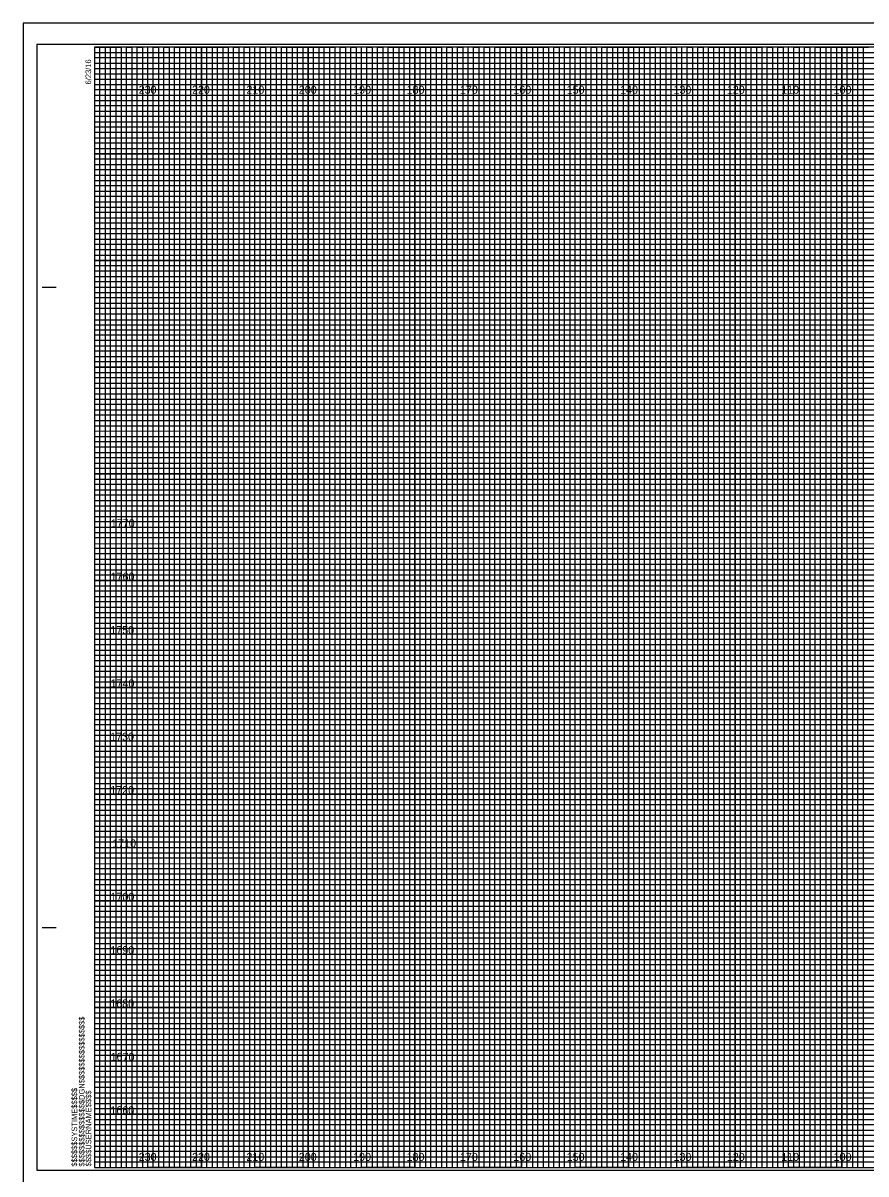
# Model space of a CAD drawing. Extents: x -13 to 1780, y -15 to 3284.
# Drawn here: x 726.7 to 884.6, y 214.9 to 430.6 of the extents above; entities that cross this region are included whole.
import ezdxf

# ---------------------------------------------------------------- set-up
doc = ezdxf.new("R2010")
doc.units = 0
for name, color, linetype in [('Prop Retaining Wall', 7, 'Continuous'), ('Prop SS Cut Line', 7, 'Continuous'), ('Prop SS Fill Line', 7, 'Continuous'), ('Prop SS Transition Line', 7, 'Continuous'), ('Prop XS Earthwork Shape', 7, 'Continuous'), ('Prop XS Noise Wall', 7, 'Continuous'), ('Prop XS Station Labels', 7, 'Continuous'), ('Raster_Level_0', 7, 'Continuous'), ('Scratch_Level_3', 7, 'Continuous'), ('Scratch_Level_7', 7, 'Continuous'), ('Typical Bridge Rail CELL', 7, 'Continuous')]:
    doc.layers.add(name, color=color, linetype=linetype)

msp = doc.modelspace()

# ---------------------------------------------------------------- linework, layer by layer
at = {"layer": 'Prop Retaining Wall'}
for p, q in [((730.26, 381.12), (732.76, 381.12)), ((730.36, 381.12), (732.86, 381.12)), ((730.26, 261.12), (732.76, 261.12)), ((730.36, 261.12), (732.86, 261.12)), ((740.06, 216.12), (740.06, 216.12)), ((740.06, 216.12), (740.06, 216.12)), ((740.06, 216.12), (740.06, 216.12)), ((740.06, 216.12), (740.06, 216.12)), ((740.06, 216.12), (740.06, 216.12)), ((740.06, 216.12), (740.06, 216.12)), ((740.06, 216.12), (740.06, 216.12))]:
    msp.add_line(p, q, dxfattribs=at)
msp.add_lwpolyline([(1060.06, 426.12), (740.06, 426.12), (740.06, 216.12), (1060.06, 216.12)], close=True, dxfattribs=at)
at = {"layer": 'Prop SS Cut Line'}
for points in [[(740.06, 426.12), (745.06, 426.12), (745.06, 216.12), (755.06, 216.12), (755.06, 426.12), (765.06, 426.12), (765.06, 216.12), (775.06, 216.12), (775.06, 426.12), (785.06, 426.12), (785.06, 216.12), (795.06, 216.12), (795.06, 426.12), (805.06, 426.12), (805.06, 216.12), (815.06, 216.12), (815.06, 426.12), (825.06, 426.12), (825.06, 216.12), (835.06, 216.12), (835.06, 426.12), (845.06, 426.12), (845.06, 216.12), (855.06, 216.12), (855.06, 426.12), (865.06, 426.12), (865.06, 216.12), (875.06, 216.12), (875.06, 426.12), (885.06, 426.12)], [(740.06, 421.12), (1015.06, 421.12)], [(740.06, 401.12), (1060.06, 401.12), (1060.06, 411.12), (740.06, 411.12)], [(740.06, 381.12), (1060.06, 381.12), (1060.06, 391.12), (740.06, 391.12)], [(740.06, 361.12), (1060.06, 361.12), (1060.06, 371.12), (740.06, 371.12)], [(740.06, 341.12), (1060.06, 341.12), (1060.06, 351.12), (740.06, 351.12)], [(740.06, 321.12), (1060.06, 321.12), (1060.06, 331.12), (740.06, 331.12)], [(740.06, 301.12), (1060.06, 301.12), (1060.06, 311.12), (740.06, 311.12)], [(740.06, 281.12), (1060.06, 281.12), (1060.06, 291.12), (740.06, 291.12)], [(740.06, 261.12), (1060.06, 261.12), (1060.06, 271.12), (740.06, 271.12)], [(740.06, 241.12), (1060.06, 241.12), (1060.06, 251.12), (740.06, 251.12)], [(740.06, 221.12), (1060.06, 221.12), (1060.06, 231.12), (740.06, 231.12)]]:
    msp.add_lwpolyline(points, dxfattribs=at)
at = {"layer": 'Prop SS Fill Line'}
for p, q in [((750.06, 426.12), (740.06, 426.12)), ((750.06, 216.12), (750.06, 426.12)), ((770.06, 426.12), (760.06, 426.12)), ((760.06, 426.12), (760.06, 216.12)), ((770.06, 216.12), (770.06, 426.12)), ((790.06, 426.12), (780.06, 426.12)), ((780.06, 426.12), (780.06, 216.12)), ((790.06, 216.12), (790.06, 426.12)), ((810.06, 426.12), (800.06, 426.12)), ((800.06, 426.12), (800.06, 216.12)), ((810.06, 216.12), (810.06, 426.12)), ((830.06, 426.12), (820.06, 426.12)), ((820.06, 426.12), (820.06, 216.12)), ((830.06, 216.12), (830.06, 426.12)), ((850.06, 426.12), (840.06, 426.12)), ((840.06, 426.12), (840.06, 216.12)), ((850.06, 216.12), (850.06, 426.12)), ((870.06, 426.12), (860.06, 426.12)), ((860.06, 426.12), (860.06, 216.12)), ((870.06, 216.12), (870.06, 426.12)), ((890.06, 426.12), (880.06, 426.12)), ((880.06, 426.12), (880.06, 216.12)), ((760.06, 216.12), (750.06, 216.12)), ((780.06, 216.12), (770.06, 216.12)), ((800.06, 216.12), (790.06, 216.12)), ((820.06, 216.12), (810.06, 216.12)), ((840.06, 216.12), (830.06, 216.12)), ((860.06, 216.12), (850.06, 216.12)), ((880.06, 216.12), (870.06, 216.12))]:
    msp.add_line(p, q, dxfattribs=at)
for points in [[(740.06, 416.12), (1060.06, 416.12), (1060.06, 406.12), (740.06, 406.12)], [(740.06, 396.12), (1060.06, 396.12), (1060.06, 386.12), (740.06, 386.12)], [(740.06, 376.12), (1060.06, 376.12), (1060.06, 366.12), (740.06, 366.12)], [(740.06, 356.12), (1060.06, 356.12), (1060.06, 346.12), (740.06, 346.12)], [(740.06, 336.12), (1060.06, 336.12), (1060.06, 326.12), (740.06, 326.12)], [(740.06, 316.12), (1060.06, 316.12), (1060.06, 306.12), (740.06, 306.12)], [(740.06, 296.12), (1060.06, 296.12), (1060.06, 286.12), (740.06, 286.12)], [(740.06, 276.12), (1060.06, 276.12), (1060.06, 266.12), (740.06, 266.12)], [(740.06, 256.12), (1060.06, 256.12), (1060.06, 246.12), (740.06, 246.12)], [(740.06, 236.12), (1060.06, 236.12), (1060.06, 226.12), (740.06, 226.12)]]:
    msp.add_lwpolyline(points, dxfattribs=at)
at = {"layer": 'Prop SS Transition Line'}
for p, q in [((740.06, 425.12), (1000.06, 425.12)), ((1000.06, 424.1), (740.06, 424.1)), ((740.06, 424.1), (740.06, 423.12)), ((740.06, 423.12), (1000.06, 423.12)), ((1000.06, 422.01), (740.06, 422.01)), ((740.06, 422.01), (740.06, 420.12)), ((740.06, 420.12), (1060.06, 420.12))]:
    msp.add_line(p, q, dxfattribs=at)
for points in [[(740.06, 419.12), (1010.06, 419.12), (1060.06, 419.12), (1060.06, 418.12), (740.06, 418.12)], [(740.06, 417.12), (1060.06, 417.12), (1060.06, 415.12), (740.06, 415.12)], [(740.06, 414.12), (1060.06, 414.12), (1060.06, 413.12), (740.06, 413.1)], [(740.06, 412.12), (1060.06, 412.12), (1060.06, 410.12), (740.06, 410.12)], [(740.06, 409.12), (1060.06, 409.12), (1060.06, 408.12), (740.06, 408.12)], [(740.06, 407.12), (1060.06, 407.12), (1060.06, 405.12), (740.06, 405.12)], [(740.06, 404.12), (1060.06, 404.12), (1060.06, 403.12), (740.06, 403.12)], [(740.06, 402.12), (1060.06, 402.12), (1060.06, 400.12), (740.06, 400.12)], [(740.06, 399.12), (1060.06, 399.12), (1060.06, 398.12), (740.06, 398.12)], [(740.06, 397.12), (1060.06, 397.12), (1060.06, 395.12), (740.06, 395.12)], [(740.06, 394.12), (1060.06, 394.12), (1060.06, 393.12), (740.06, 393.12)], [(740.06, 392.12), (1060.06, 392.12), (1060.06, 390.07), (1060.06, 389.12), (1060.06, 388.12), (740.06, 388.12)], [(740.06, 390.12), (1060.06, 390.12), (1060.06, 389.12), (740.06, 389.12)], [(740.06, 387.12), (1060.06, 387.12), (1060.06, 385.12), (740.06, 385.15)], [(740.06, 385.15), (1060.06, 385.12), (1060.06, 384.12), (740.06, 384.12)], [(740.06, 383.12), (1060.06, 383.12), (1060.06, 382.12), (740.06, 382.12)], [(740.06, 380.12), (1060.06, 380.12), (1060.06, 379.12), (740.06, 379.12)], [(740.06, 378.12), (1060.06, 378.12), (1060.06, 377.12), (740.06, 377.12)], [(739.99, 375.01), (1060.06, 375.01), (1060.06, 374), (739.99, 374)], [(740.06, 373.12), (1060.06, 373.12), (1060.06, 372.12), (740.06, 372.12)], [(740.06, 370.12), (1060.06, 370.12), (1060.06, 369.12), (740.06, 369.12)], [(740.06, 368.12), (1060.06, 368.12), (1060.06, 367.12), (740.06, 367.12)], [(740.06, 365.12), (1060.06, 365.12), (1060.06, 364.12), (740.06, 364.12)], [(740.06, 363.12), (1060.06, 363.12), (1060.06, 362.12), (740.06, 362.12)], [(740.06, 360.12), (1060.06, 360.12), (1060.06, 359.12), (740.06, 359.12)], [(740.06, 358.12), (1060.06, 358.12), (1060.06, 357.12), (740.06, 357.12)], [(740.06, 355.12), (1060.06, 355.12), (1060.05, 354.1), (740.06, 354.12)], [(740.06, 353.12), (1060.06, 353.12), (1060.06, 352.12), (740.06, 352.12)], [(740.06, 350.12), (1060.06, 350.12), (1060.06, 349.12), (740.06, 349.12)], [(740.06, 348.12), (1060.06, 348.12), (1060.06, 347.12), (740.06, 347.12)], [(740.06, 345.12), (1060.06, 345.12), (1060.06, 344.12), (740.06, 344.12)], [(740.06, 343.12), (1060.06, 343.12), (1060.06, 342.12), (740.06, 342.12)], [(740.06, 340.12), (1060.06, 340.12), (1060.06, 339.12), (740.06, 339.12)], [(740.06, 338.12), (1060.06, 338.12), (1060.06, 337.12), (740.06, 337.12)], [(740.06, 335.12), (1060.06, 335.12), (1060.06, 334.12), (740.06, 334.12)], [(740.06, 333.11), (1060.13, 333.03), (1060.06, 332.12), (740.06, 332.12)], [(740.06, 330.12), (1060.06, 330.12), (1060.06, 329.12), (740.06, 329.12)], [(740.06, 328.12), (1060.06, 328.12), (1060.06, 327.12), (740.06, 327.12)], [(740.06, 325.12), (1060.06, 325.12), (1060.06, 324.12), (740.06, 324.12)], [(740.06, 323.12), (1060.06, 323.12), (1060.06, 322.12), (740.06, 322.12)], [(740.06, 320.12), (1060.06, 320.12), (1060.06, 319.12), (740.06, 319.12)], [(740.06, 318.12), (1060.06, 318.12), (1060.06, 317.12), (740.06, 317.12)], [(740.06, 315.12), (1060.06, 315.12), (1060.06, 314.12), (740.06, 314.12)], [(740.06, 313.12), (1060.06, 313.12), (1060.06, 312.12), (740.06, 312.12)], [(740.06, 310.12), (1060.06, 310.12), (1060.06, 309.12), (740.06, 309.12)], [(740.06, 308.12), (1060.06, 308.12), (1060.06, 307.12), (740.06, 307.12)], [(740.06, 305.12), (1060.06, 305.12), (1060.06, 304.12), (740.06, 304.12)], [(740.06, 303.12), (1060.06, 303.12), (1060.06, 302.12), (740.06, 302.12)], [(740.06, 300.12), (1060.06, 300.12), (1060.06, 299.12), (740.06, 299.12)], [(740.06, 298.12), (1060.06, 298.12), (1060.06, 297.12), (740.06, 297.12)], [(740.06, 295.12), (1060.06, 295.12), (1060.05, 294.1), (740.06, 294.12)], [(740.06, 293.12), (1060.06, 293.12), (1060.06, 292.12), (740.06, 292.12)], [(740.06, 290.12), (1060.06, 290.12), (1060.06, 289.12), (740.06, 289.12)], [(740.06, 288.12), (1060.06, 288.12), (1060.06, 287.12), (740.06, 287.12)], [(740.06, 285.12), (1060.06, 285.12), (1060.06, 284.12), (740.06, 284.12)], [(740.06, 283.12), (1060.06, 283.12), (1060.06, 282.12), (740.06, 282.12)], [(740.06, 280.12), (1060.06, 280.12), (1060.06, 279.12), (740.06, 279.12)], [(740.06, 278.12), (1060.06, 278.12), (1060.06, 277.12), (740.06, 277.12)], [(740.06, 275.12), (1060.06, 275.12), (1060.06, 274.12), (740.06, 274.12)], [(740.06, 273.11), (1060.13, 273.03), (1060.06, 272.12), (740.06, 272.12)], [(740.06, 270.12), (1060.06, 270.12), (1060.06, 269.12), (740.06, 269.12)], [(740.06, 268.12), (1060.06, 268.12), (1060.06, 267.12), (740.06, 267.12)], [(740.06, 265.12), (1060.06, 265.12), (1060.06, 264.12), (740.06, 264.12)], [(740.06, 263.12), (1060.06, 263.12), (1060.06, 262.12), (740.06, 262.12)], [(740.06, 260.12), (1060.06, 260.12), (1060.06, 259.12), (740.06, 259.12)], [(740.06, 258.12), (1060.06, 258.12), (1060.06, 257.12), (740.06, 257.12)], [(740.06, 255.12), (1060.06, 255.12), (1060.06, 254.12), (740.06, 254.12)], [(740.06, 253.12), (1060.06, 253.12), (1060.06, 252.12), (740.06, 252.12)], [(740.06, 250.12), (1060.06, 250.12), (1060.06, 249.12), (740.06, 249.12)], [(740.06, 248.12), (1060.06, 248.12), (1060.06, 247.12), (740.06, 247.12)], [(740.06, 245.12), (1060.06, 245.12), (1060.06, 244.12), (740.06, 244.12)], [(740.06, 243.12), (1060.06, 243.12), (1060.06, 242.12), (740.06, 242.12)], [(740.06, 240.12), (1060.06, 240.12), (1060.06, 239.12), (740.06, 239.12)], [(740.06, 238.12), (1060.06, 238.12), (1060.06, 237.12), (740.06, 237.12)], [(740.06, 235.12), (1060.06, 235.12), (1060.06, 234.12), (740.06, 234.12)], [(740.06, 233.12), (1060.06, 233.12), (1060.06, 232.12), (740.06, 232.12)], [(740.06, 230.12), (1060.06, 230.12), (1060.06, 229.12), (740.06, 229.12)], [(740.06, 228.12), (1060.06, 228.12), (1060.06, 227.12), (740.06, 227.12)], [(740.06, 225.12), (1060.06, 225.12), (1060.06, 224.12), (740.06, 224.12)], [(740.06, 223.12), (1060.06, 223.12), (1060.06, 222.12), (740.06, 222.12)], [(740.06, 220.12), (1060.06, 220.12), (1060.06, 219.12), (740.06, 219.12)], [(740.06, 218.12), (1060.06, 218.12), (1060.06, 217.12), (740.06, 217.12)]]:
    msp.add_lwpolyline(points, dxfattribs=at)
at = {"layer": 'Prop XS Earthwork Shape'}
msp.add_lwpolyline([(726.66, 211.62), (1063.36, 211.62), (1063.36, 430.62), (726.66, 430.62)], close=True, dxfattribs=at)
at = {"layer": 'Prop XS Noise Wall'}
for p, q in [((750.06, 216.12), (750.06, 426.12)), ((760.06, 216.12), (760.06, 426.12)), ((770.06, 216.12), (770.06, 426.12)), ((780.06, 216.12), (780.06, 426.12)), ((790.06, 216.12), (790.06, 426.12)), ((800.06, 216.12), (800.06, 426.12)), ((810.06, 216.12), (810.06, 426.12)), ((820.06, 216.12), (820.06, 426.12)), ((830.06, 216.12), (830.06, 426.12)), ((840.06, 216.12), (840.06, 426.12)), ((850.06, 216.12), (850.06, 426.12)), ((860.06, 216.12), (860.06, 426.12)), ((870.06, 216.12), (870.06, 426.12)), ((880.06, 216.12), (880.06, 426.12)), ((740.06, 416.12), (1060.06, 416.12)), ((740.06, 406.12), (1060.06, 406.12)), ((740.06, 396.12), (1060.06, 396.12)), ((740.06, 386.12), (1060.06, 386.12)), ((740.06, 376.12), (1060.06, 376.12)), ((740.06, 366.12), (1060.06, 366.12)), ((740.06, 356.12), (1060.06, 356.12)), ((740.06, 346.12), (1060.06, 346.12)), ((740.06, 336.12), (1060.06, 336.12)), ((740.06, 326.12), (1060.06, 326.12)), ((740.06, 316.12), (1060.06, 316.12)), ((740.06, 306.12), (1060.06, 306.12)), ((740.06, 296.12), (1060.06, 296.12)), ((740.06, 286.12), (1060.06, 286.12)), ((740.06, 276.12), (1060.06, 276.12)), ((740.06, 266.12), (1060.06, 266.12)), ((740.06, 256.12), (1060.06, 256.12)), ((740.06, 246.12), (1060.06, 246.12)), ((740.06, 236.12), (1060.06, 236.12)), ((740.06, 226.12), (1060.06, 226.12))]:
    msp.add_line(p, q, dxfattribs=at)
at = {"layer": 'Prop XS Station Labels'}
for p, q in [((1063.36, 430.62), (726.66, 430.62)), ((726.66, 430.62), (726.66, 211.62))]:
    msp.add_line(p, q, dxfattribs=at)
at = {"layer": 'Scratch_Level_7'}
msp.add_lwpolyline([(729.26, 215.62), (1062.46, 215.62), (1062.46, 426.62), (729.26, 426.62)], close=True, dxfattribs=at)
at = {"layer": 'Typical Bridge Rail CELL'}
for points in [[(740.06, 216.12), (741.06, 216.12), (741.06, 426.12), (742.06, 426.12), (742.06, 216.12)], [(742.06, 216.12), (743.06, 216.12), (743.06, 426.12), (744.06, 426.12), (744.06, 216.12)], [(745.06, 216.12), (746.06, 216.12), (746.06, 426.12), (747.06, 426.12), (747.06, 216.12)], [(747.06, 216.12), (748.06, 216.12), (748.06, 426.12), (749.06, 426.12), (749.06, 216.12)], [(750.06, 216.12), (751.06, 216.12), (751.06, 426.12), (752.06, 426.12), (752.06, 216.12)], [(752.06, 216.12), (753.06, 216.12), (753.06, 426.12), (754.06, 426.12), (754.06, 216.12)], [(755.06, 216.12), (756.06, 216.12), (756.06, 426.12), (757.06, 426.12), (757.06, 216.12)], [(757.06, 216.12), (758.06, 216.12), (758.06, 426.12), (759.06, 426.12), (759.06, 216.12)], [(760.06, 216.12), (761.06, 216.12), (761.06, 426.12), (762.06, 426.12), (762.06, 216.12)], [(762.06, 216.12), (763.06, 216.12), (763.06, 426.12), (764.06, 426.12), (764.06, 216.12)], [(765.06, 216.12), (766.06, 216.12), (766.06, 426.12), (767.06, 426.12), (767.06, 216.12)], [(767.06, 216.12), (768.06, 216.12), (768.06, 426.12), (769.06, 426.12), (769.06, 216.12)], [(770.06, 216.12), (771.06, 216.12), (771.06, 426.12), (772.06, 426.12), (772.06, 216.12)], [(772.06, 216.12), (773.06, 216.12), (773.06, 426.12), (774.06, 426.12), (774.06, 216.12)], [(775.06, 216.12), (776.06, 216.12), (776.06, 426.12), (777.06, 426.12), (777.06, 216.12)], [(777.06, 216.12), (778.06, 216.12), (778.06, 426.12), (779.06, 426.12), (779.06, 216.12)], [(780.06, 216.12), (781.06, 216.12), (781.06, 426.12), (782.06, 426.12), (782.06, 216.12)], [(782.06, 216.12), (783.06, 216.12), (783.06, 426.12), (784.06, 426.12), (784.06, 216.12)], [(785.06, 216.12), (786.06, 216.12), (786.06, 426.12), (787.06, 426.12), (787.06, 216.12)], [(787.06, 216.12), (788.06, 216.12), (788.06, 426.12), (789.06, 426.12), (789.06, 216.12)], [(790.06, 216.12), (791.06, 216.12), (791.06, 426.12), (792.06, 426.12), (792.06, 216.12)], [(792.06, 216.12), (793.06, 216.12), (793.06, 426.12), (794.06, 426.12), (794.06, 216.12)], [(795.06, 216.12), (796.06, 216.12), (796.06, 426.12), (797.06, 426.12), (797.06, 216.12)], [(797.06, 216.12), (798.06, 216.12), (798.06, 426.12), (799.06, 426.12), (799.06, 216.12)], [(800.06, 216.12), (801.06, 216.12), (801.06, 426.12), (802.06, 426.12), (802.06, 216.12)], [(802.06, 216.12), (803.06, 216.12), (803.06, 426.12), (804.06, 426.12), (804.06, 216.12)], [(805.06, 216.12), (806.06, 216.12), (806.06, 426.12), (807.06, 426.12), (807.06, 216.12)], [(807.06, 216.12), (808.06, 216.12), (808.06, 426.12), (809.06, 426.12), (809.06, 216.12)], [(810.06, 216.12), (811.06, 216.12), (811.06, 426.12), (812.06, 426.12), (812.06, 216.12)], [(812.06, 216.12), (813.06, 216.12), (813.06, 426.12), (814.06, 426.12), (814.06, 216.12)], [(815.06, 216.12), (816.06, 216.12), (816.06, 426.12), (817.06, 426.12), (817.06, 216.12)], [(817.06, 216.12), (818.06, 216.12), (818.06, 426.12), (819.06, 426.12), (819.06, 216.12)], [(820.06, 216.12), (821.06, 216.12), (821.06, 426.12), (822.06, 426.12), (822.06, 216.12)], [(822.06, 216.12), (823.06, 216.12), (823.06, 426.12), (824.06, 426.12), (824.06, 216.12)], [(825.06, 216.12), (826.06, 216.12), (826.06, 426.12), (827.06, 426.12), (827.06, 216.12)], [(827.06, 216.12), (828.06, 216.12), (828.06, 426.12), (829.06, 426.12), (829.06, 216.12)], [(830.06, 216.12), (831.06, 216.12), (831.06, 426.12), (832.06, 426.12), (832.06, 216.12)], [(832.06, 216.12), (833.06, 216.12), (833.06, 426.12), (834.06, 426.12), (834.06, 216.12)], [(835.06, 216.12), (836.06, 216.12), (836.06, 426.12), (837.06, 426.12), (837.06, 216.12)], [(837.06, 216.12), (838.06, 216.12), (838.06, 426.12), (839.06, 426.12), (839.06, 216.12)], [(840.06, 216.12), (841.06, 216.12), (841.06, 426.12), (842.06, 426.12), (842.06, 216.12)], [(842.06, 216.12), (843.06, 216.12), (843.06, 426.12), (844.06, 426.12), (844.06, 216.12)], [(845.06, 216.12), (846.06, 216.12), (846.06, 426.12), (847.06, 426.12), (847.06, 216.12)], [(847.06, 216.12), (848.06, 216.12), (848.06, 426.12), (849.06, 426.12), (849.06, 216.12)], [(850.06, 216.12), (851.06, 216.12), (851.06, 426.12), (852.06, 426.12), (852.06, 216.12)], [(852.06, 216.12), (853.06, 216.12), (853.06, 426.12), (854.06, 426.12), (854.06, 216.12)], [(855.06, 216.12), (856.06, 216.12), (856.06, 426.12), (857.06, 426.12), (857.06, 216.12)], [(857.06, 216.12), (858.06, 216.12), (858.06, 426.12), (859.06, 426.12), (859.06, 216.12)], [(860.06, 216.12), (861.06, 216.12), (861.06, 426.12), (862.06, 426.12), (862.06, 216.12)], [(862.06, 216.12), (863.06, 216.12), (863.06, 426.12), (864.06, 426.12), (864.06, 216.12)], [(865.06, 216.12), (866.06, 216.12), (866.06, 426.12), (867.06, 426.12), (867.06, 216.12)], [(867.06, 216.12), (868.06, 216.12), (868.06, 426.12), (869.06, 426.12), (869.06, 216.12)], [(870.06, 216.12), (871.06, 216.12), (871.06, 426.12), (872.06, 426.12), (872.06, 216.12)], [(872.06, 216.12), (873.06, 216.12), (873.06, 426.12), (874.06, 426.12), (874.06, 216.12)], [(875.06, 216.12), (876.06, 216.12), (876.06, 426.12), (877.06, 426.12), (877.06, 216.12)], [(877.06, 216.12), (878.06, 216.12), (878.06, 426.12), (879.06, 426.12), (879.06, 216.12)], [(880.06, 216.12), (881.06, 216.12), (881.06, 426.12), (882.06, 426.12), (882.06, 216.12)], [(882.06, 216.12), (883.06, 216.12), (883.06, 426.12), (884.06, 426.12), (884.06, 216.12)]]:
    msp.add_lwpolyline(points, dxfattribs=at)

# ---------------------------------------------------------------- texts
at = {"layer": 'Prop Retaining Wall'}
for s, p in [('6/23/16', (739.41, 419.12)), ('$$$$$$$$$$$$$$$$DGN$$$$$$$$$$$$$$$$', (738.18, 216.3)), ('$$$$$$SYSTIME$$$$$', (736.8, 216.3)), ('$$$$USERNAME$$$$', (739.44, 216.35))]:
    msp.add_text(s, height=1.05, rotation=90, dxfattribs=at).set_placement(p)
at = {"layer": 'Raster_Level_0'}
for s, p in [('230', (748.32, 417.37)), ('220', (758.32, 417.37)), ('210', (768.5, 417.37)), ('200', (778.32, 417.37)), ('190', (788.5, 417.37)), ('180', (798.5, 417.37)), ('170', (808.5, 417.37)), ('160', (818.5, 417.37)), ('150', (828.5, 417.37)), ('140', (838.5, 417.37)), ('130', (848.5, 417.37)), ('120', (858.5, 417.37)), ('110', (868.68, 417.37)), ('100', (878.5, 417.37)), ('230', (748.32, 217.37)), ('220', (758.32, 217.37)), ('210', (768.5, 217.37)), ('200', (778.32, 217.37)), ('190', (788.5, 217.37)), ('180', (798.5, 217.37)), ('170', (808.5, 217.37)), ('160', (818.5, 217.37)), ('150', (828.5, 217.37)), ('140', (838.5, 217.37)), ('130', (848.5, 217.37)), ('120', (858.5, 217.37)), ('110', (868.68, 217.37)), ('100', (878.5, 217.37))]:
    msp.add_text(s, height=1.5, dxfattribs=at).set_placement(p)
at = {"layer": 'Scratch_Level_3'}
for s, p in [('1770', (743.1, 336.12)), ('1760', (743.06, 326.12)), ('1750', (743.01, 316.12)), ('1740', (743.06, 306.12)), ('1730', (742.98, 296.12)), ('1720', (742.99, 286.12)), ('1710', (743.37, 276.12)), ('1700', (743.04, 266.12)), ('1690', (743.03, 256.12)), ('1680', (743, 246.12)), ('1670', (743.06, 236.12)), ('1660', (743.03, 226.12))]:
    msp.add_text(s, height=1.5, dxfattribs=at).set_placement(p)

doc.saveas('drawing.dxf')
